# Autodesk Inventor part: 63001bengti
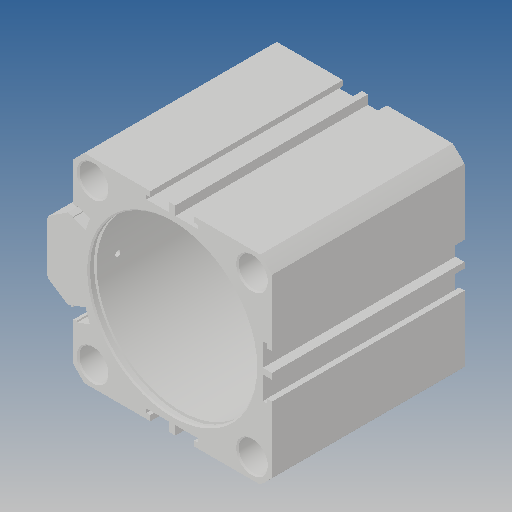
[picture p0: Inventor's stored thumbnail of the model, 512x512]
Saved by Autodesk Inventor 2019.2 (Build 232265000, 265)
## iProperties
Created: 2013-07
Part Number: 63001bengti
Material: Ogólny
Document SubType Name: Modeling
Designer: CADENGINEERING4
Density: 1 g/cm^3
Appearance: Domyślna
Author: CADENGINEERING4
Revision Number: ÈÎºÎ
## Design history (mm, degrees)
feature "µ¹½Ç6"
node "Bryła1"
